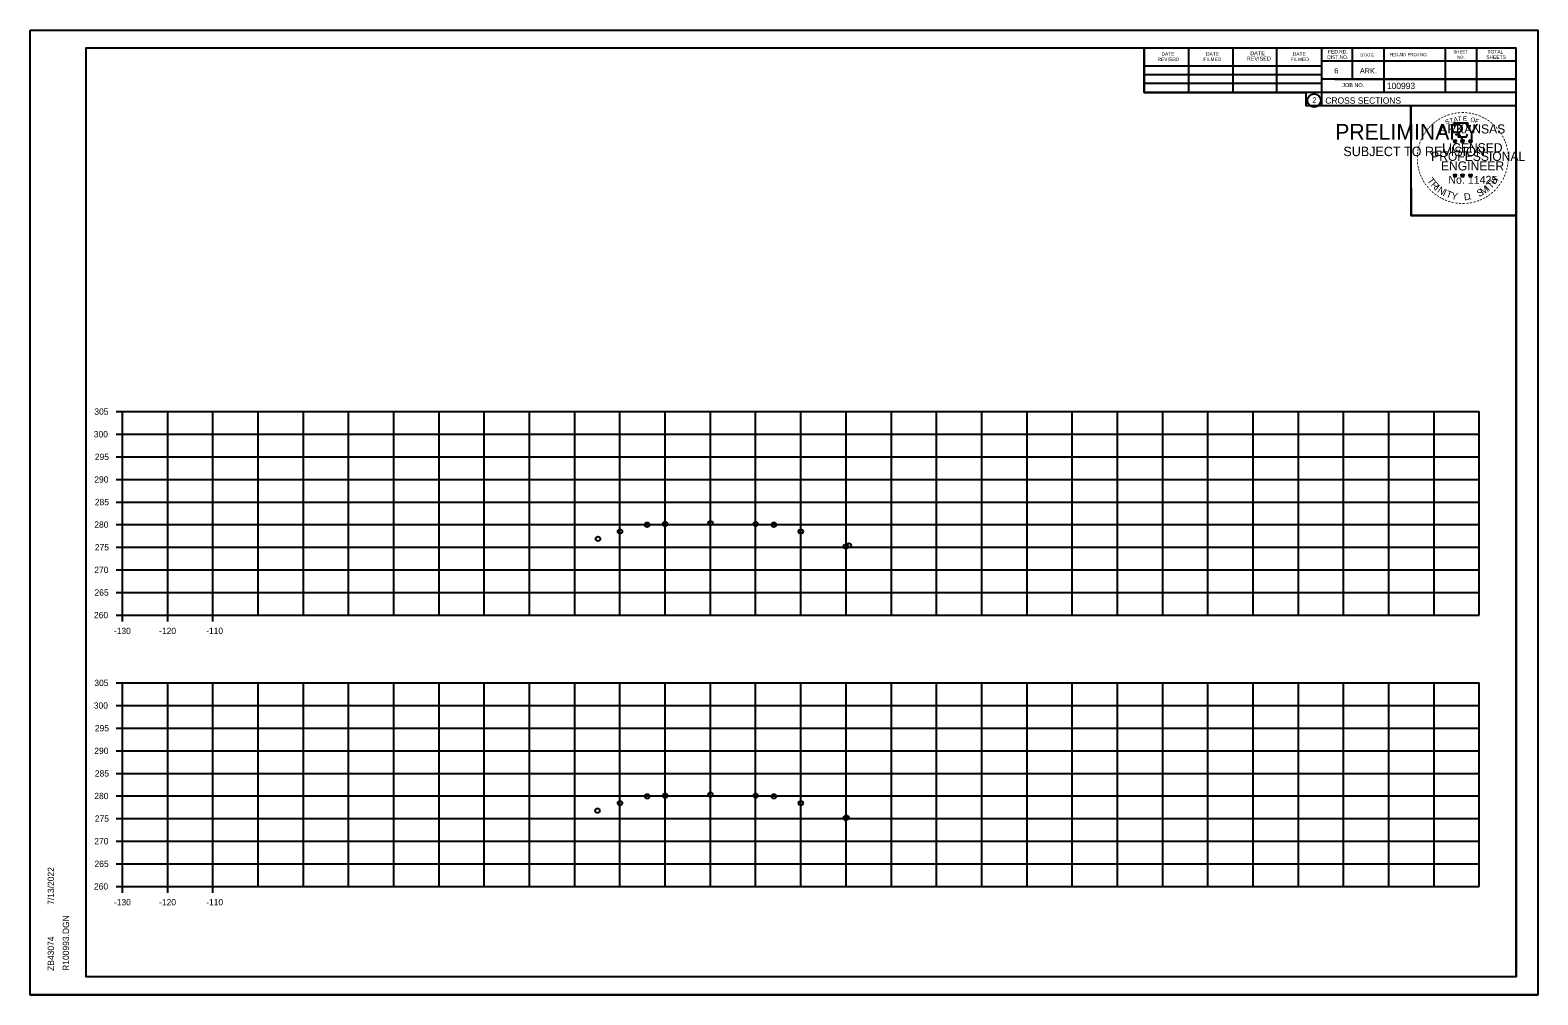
# Model space of a CAD drawing. Extents: x 4667 to 1632277, y -2100 to 724501.
# Drawn here: x 5969.1 to 6302.5, y -257.1 to -43.7 of the extents above; entities that cross this region are included whole.
import ezdxf

# ---------------------------------------------------------------- set-up
doc = ezdxf.new("R2010")
doc.units = 0
for name, color, linetype in [('R_Axis', 7, 'Continuous'), ('R_Axis Annot', 7, 'Continuous'), ('R_Grid', 7, 'Continuous'), ('R_No Plot', 7, 'Continuous')]:
    doc.layers.add(name, color=color, linetype=linetype)

msp = doc.modelspace()

# ---------------------------------------------------------------- linework, layer by layer
at = {"layer": 'R_Axis'}
for p, q in [((5988.12, -128.08), (5989.52, -128.08)), ((5989.52, -173.08), (5989.52, -128.08)), ((5988.12, -133.08), (5989.52, -133.08)), ((5988.12, -138.08), (5989.52, -138.08)), ((5988.12, -143.08), (5989.52, -143.08)), ((5988.12, -148.08), (5989.52, -148.08)), ((5988.12, -153.08), (5989.52, -153.08)), ((5988.12, -158.08), (5989.52, -158.08)), ((5988.12, -163.08), (5989.52, -163.08)), ((5988.12, -168.08), (5989.52, -168.08)), ((5988.12, -173.08), (5989.52, -173.08)), ((5989.52, -174.48), (5989.52, -173.08)), ((5999.52, -174.48), (5999.52, -173.08)), ((6009.52, -174.48), (6009.52, -173.08)), ((5988.12, -188.08), (5989.52, -188.08)), ((5989.52, -233.08), (5989.52, -188.08)), ((5988.12, -193.08), (5989.52, -193.08)), ((5988.12, -198.08), (5989.52, -198.08)), ((5988.12, -203.08), (5989.52, -203.08)), ((5988.12, -208.08), (5989.52, -208.08)), ((5988.12, -213.08), (5989.52, -213.08)), ((5988.12, -218.08), (5989.52, -218.08)), ((5988.12, -223.08), (5989.52, -223.08)), ((5988.12, -228.08), (5989.52, -228.08)), ((5988.12, -233.08), (5989.52, -233.08)), ((5989.52, -234.48), (5989.52, -233.08)), ((5999.52, -234.48), (5999.52, -233.08)), ((6009.52, -234.48), (6009.52, -233.08))]:
    msp.add_line(p, q, dxfattribs=at)
at = {"layer": 'R_Grid'}
for p, q in [((5989.52, -128.08), (6289.52, -128.08)), ((5989.52, -173.08), (5989.52, -128.08)), ((5999.52, -173.08), (5999.52, -128.08)), ((6009.52, -173.08), (6009.52, -128.08)), ((6019.52, -173.08), (6019.52, -128.08)), ((6029.52, -173.08), (6029.52, -128.08)), ((6039.52, -173.08), (6039.52, -128.08)), ((6049.52, -173.08), (6049.52, -128.08)), ((6059.52, -173.08), (6059.52, -128.08)), ((6069.52, -173.08), (6069.52, -128.08)), ((6079.52, -173.08), (6079.52, -128.08)), ((6089.52, -173.08), (6089.52, -128.08)), ((6099.52, -173.08), (6099.52, -128.08)), ((6109.52, -173.08), (6109.52, -128.08)), ((6119.52, -173.08), (6119.52, -128.08)), ((6129.52, -173.08), (6129.52, -128.08)), ((6139.52, -173.08), (6139.52, -128.08)), ((6149.52, -173.08), (6149.52, -128.08)), ((6159.52, -173.08), (6159.52, -128.08)), ((6169.52, -173.08), (6169.52, -128.08)), ((6179.52, -173.08), (6179.52, -128.08)), ((6189.52, -173.08), (6189.52, -128.08)), ((6199.52, -173.08), (6199.52, -128.08)), ((6209.52, -173.08), (6209.52, -128.08)), ((6219.52, -173.08), (6219.52, -128.08)), ((6229.52, -173.08), (6229.52, -128.08)), ((6239.52, -173.08), (6239.52, -128.08)), ((6249.52, -173.08), (6249.52, -128.08)), ((6259.52, -173.08), (6259.52, -128.08)), ((6269.52, -173.08), (6269.52, -128.08)), ((6279.52, -173.08), (6279.52, -128.08)), ((6289.52, -173.08), (6289.52, -128.08)), ((5989.52, -133.08), (6289.52, -133.08)), ((5989.52, -138.08), (6289.52, -138.08)), ((5989.52, -143.08), (6289.52, -143.08)), ((5989.52, -148.08), (6289.52, -148.08)), ((5989.52, -153.08), (6289.52, -153.08)), ((5989.52, -158.08), (6289.52, -158.08)), ((5989.52, -163.08), (6289.52, -163.08)), ((5989.52, -168.08), (6289.52, -168.08)), ((5989.52, -173.08), (6289.52, -173.08)), ((5989.52, -188.08), (6289.52, -188.08)), ((5989.52, -233.08), (5989.52, -188.08)), ((5999.52, -233.08), (5999.52, -188.08)), ((6009.52, -233.08), (6009.52, -188.08)), ((6019.52, -233.08), (6019.52, -188.08)), ((6029.52, -233.08), (6029.52, -188.08)), ((6039.52, -233.08), (6039.52, -188.08)), ((6049.52, -233.08), (6049.52, -188.08)), ((6059.52, -233.08), (6059.52, -188.08)), ((6069.52, -233.08), (6069.52, -188.08)), ((6079.52, -233.08), (6079.52, -188.08)), ((6089.52, -233.08), (6089.52, -188.08)), ((6099.52, -233.08), (6099.52, -188.08)), ((6109.52, -233.08), (6109.52, -188.08)), ((6119.52, -233.08), (6119.52, -188.08)), ((6129.52, -233.08), (6129.52, -188.08)), ((6139.52, -233.08), (6139.52, -188.08)), ((6149.52, -233.08), (6149.52, -188.08)), ((6159.52, -233.08), (6159.52, -188.08)), ((6169.52, -233.08), (6169.52, -188.08)), ((6179.52, -233.08), (6179.52, -188.08)), ((6189.52, -233.08), (6189.52, -188.08)), ((6199.52, -233.08), (6199.52, -188.08)), ((6209.52, -233.08), (6209.52, -188.08)), ((6219.52, -233.08), (6219.52, -188.08)), ((6229.52, -233.08), (6229.52, -188.08)), ((6239.52, -233.08), (6239.52, -188.08)), ((6249.52, -233.08), (6249.52, -188.08)), ((6259.52, -233.08), (6259.52, -188.08)), ((6269.52, -233.08), (6269.52, -188.08)), ((6279.52, -233.08), (6279.52, -188.08)), ((6289.52, -233.08), (6289.52, -188.08)), ((5989.52, -193.08), (6289.52, -193.08)), ((5989.52, -198.08), (6289.52, -198.08)), ((5989.52, -203.08), (6289.52, -203.08)), ((5989.52, -208.08), (6289.52, -208.08)), ((5989.52, -213.08), (6289.52, -213.08)), ((5989.52, -218.08), (6289.52, -218.08)), ((5989.52, -223.08), (6289.52, -223.08)), ((5989.52, -228.08), (6289.52, -228.08)), ((5989.52, -233.08), (6289.52, -233.08))]:
    msp.add_line(p, q, dxfattribs=at)
at = {"layer": 'R_No Plot'}
for p, q in [((5969.12, -43.72), (6302.46, -43.72)), ((5981.52, -47.62), (6297.7, -47.62)), ((5981.52, -253.08), (5981.52, -47.62)), ((6134.04, -47.88), (6134.04, -47.88)), ((6134.04, -47.88), (6134.04, -47.88)), ((6215.44, -57.5), (6215.44, -47.62)), ((6225.3, -57.5), (6225.3, -47.82)), ((6235.06, -57.5), (6235.06, -47.82)), ((6244.74, -57.5), (6244.74, -47.82)), ((6254.6, -47.62), (6254.6, -60.42)), ((6261.44, -47.62), (6261.44, -54.56)), ((6268.38, -47.62), (6268.38, -57.5)), ((6281.96, -47.62), (6281.96, -57.5)), ((6288.9, -47.62), (6288.9, -57.5)), ((6297.7, -253.08), (6297.7, -47.62)), ((6215.44, -51.64), (6254.6, -51.64)), ((6297.7, -50.56), (6254.6, -50.56)), ((6297.7, -50.54), (6297.7, -50.54)), ((6215.44, -53.5), (6254.6, -53.5)), ((6215.44, -57.5), (6215.44, -55.44)), ((6215.44, -55.44), (6254.6, -55.44)), ((6297.7, -54.56), (6254.6, -54.56)), ((6257.56, -54.56), (6297.7, -54.56)), ((6297.7, -57.5), (6215.44, -57.5)), ((6254.6, -60.42), (6297.7, -60.42)), ((6283.79, -68.16), (6284.14, -68.27)), ((6283.79, -68.16), (6284.04, -68.21)), ((6283.79, -68.16), (6284.03, -68.29)), ((6283.92, -68.57), (6284.14, -68.27)), ((6283.92, -68.57), (6284.05, -68.33)), ((6283.92, -68.57), (6284.14, -68.35)), ((6284.14, -67.91), (6284.1, -68.16)), ((6284.14, -68.27), (6284.14, -67.91)), ((6284.14, -67.91), (6284.19, -68.16)), ((6284.49, -68.16), (6284.14, -68.27)), ((6284.35, -68.57), (6284.14, -68.27)), ((6284.35, -68.57), (6284.14, -68.36)), ((6284.49, -68.16), (6284.2, -68.21)), ((6284.35, -68.57), (6284.21, -68.28)), ((6284.49, -68.16), (6284.28, -68.27)), ((6285.46, -68.16), (6285.81, -68.27)), ((6285.46, -68.16), (6285.71, -68.21)), ((6285.46, -68.16), (6285.7, -68.29)), ((6285.59, -68.57), (6285.81, -68.27)), ((6285.59, -68.57), (6285.72, -68.33)), ((6285.59, -68.57), (6285.81, -68.35)), ((6285.81, -67.91), (6285.77, -68.16)), ((6285.81, -68.27), (6285.81, -67.91)), ((6285.81, -67.91), (6285.86, -68.16)), ((6286.16, -68.16), (6285.81, -68.27)), ((6286.02, -68.57), (6285.81, -68.27)), ((6286.02, -68.57), (6285.81, -68.36)), ((6286.16, -68.16), (6285.87, -68.21)), ((6286.02, -68.57), (6285.88, -68.28)), ((6286.16, -68.16), (6285.95, -68.27)), ((6287.22, -68.18), (6287.57, -68.29)), ((6287.22, -68.18), (6287.48, -68.22)), ((6287.22, -68.18), (6287.46, -68.3)), ((6287.36, -68.58), (6287.57, -68.29)), ((6287.36, -68.58), (6287.48, -68.34)), ((6287.36, -68.58), (6287.57, -68.37)), ((6287.57, -67.92), (6287.53, -68.17)), ((6287.57, -68.29), (6287.57, -67.92)), ((6287.57, -67.92), (6287.62, -68.17)), ((6287.92, -68.18), (6287.57, -68.29)), ((6287.79, -68.58), (6287.57, -68.29)), ((6287.79, -68.58), (6287.57, -68.37)), ((6287.92, -68.18), (6287.63, -68.22)), ((6287.79, -68.58), (6287.65, -68.29)), ((6287.92, -68.18), (6287.72, -68.28)), ((6283.79, -75.74), (6284.13, -75.85)), ((6283.79, -75.74), (6284.04, -75.78)), ((6283.79, -75.74), (6284.02, -75.86)), ((6283.92, -76.14), (6284.13, -75.85)), ((6283.92, -76.14), (6284.04, -75.9)), ((6283.92, -76.14), (6284.13, -75.93)), ((6284.13, -75.48), (6284.09, -75.73)), ((6284.13, -75.85), (6284.13, -75.48)), ((6284.13, -75.48), (6284.18, -75.73)), ((6284.48, -75.74), (6284.13, -75.85)), ((6284.35, -76.14), (6284.13, -75.85)), ((6284.35, -76.14), (6284.13, -75.93)), ((6284.48, -75.74), (6284.2, -75.79)), ((6284.35, -76.14), (6284.21, -75.85)), ((6284.48, -75.74), (6284.28, -75.84)), ((6285.45, -75.74), (6285.8, -75.85)), ((6285.45, -75.74), (6285.71, -75.78)), ((6285.45, -75.74), (6285.69, -75.86)), ((6285.59, -76.14), (6285.8, -75.85)), ((6285.59, -76.14), (6285.71, -75.9)), ((6285.59, -76.14), (6285.8, -75.93)), ((6285.8, -75.48), (6285.76, -75.73)), ((6285.8, -75.85), (6285.8, -75.48)), ((6285.8, -75.48), (6285.85, -75.73)), ((6286.15, -75.74), (6285.8, -75.85)), ((6286.02, -76.14), (6285.8, -75.85)), ((6286.02, -76.14), (6285.8, -75.93)), ((6286.15, -75.74), (6285.86, -75.79)), ((6286.02, -76.14), (6285.88, -75.85)), ((6286.15, -75.74), (6285.95, -75.84)), ((6287.22, -75.75), (6287.57, -75.86)), ((6287.22, -75.75), (6287.47, -75.79)), ((6287.22, -75.75), (6287.46, -75.87)), ((6287.35, -76.15), (6287.57, -75.86)), ((6287.35, -76.15), (6287.48, -75.91)), ((6287.35, -76.15), (6287.57, -75.94)), ((6287.57, -75.49), (6287.53, -75.74)), ((6287.57, -75.86), (6287.57, -75.49)), ((6287.57, -75.49), (6287.62, -75.74)), ((6287.92, -75.75), (6287.57, -75.86)), ((6287.78, -76.15), (6287.57, -75.86)), ((6287.78, -76.15), (6287.57, -75.94)), ((6287.92, -75.75), (6287.63, -75.8)), ((6287.78, -76.15), (6287.65, -75.86)), ((6287.92, -75.75), (6287.71, -75.85)), ((6273.74, -82.87), (6273.74, -82.87)), ((5981.52, -253.08), (5981.52, -253.08)), ((6297.7, -253.08), (5981.52, -253.08)), ((5969.12, -257.06), (6302.46, -257.06))]:
    msp.add_line(p, q, dxfattribs=at)
for points in [[(5969.12, -43.72), (6302.46, -43.72), (6302.46, -257.06), (5969.12, -257.06)], [(6215.44, -47.62), (6215.44, -57.5), (6251.18, -57.5), (6251.18, -60.42), (6274.38, -60.42), (6274.38, -84.75), (6297.7, -84.75), (6297.7, -253.08), (5981.52, -253.08), (5981.52, -47.62)], [(6274.38, -60.42), (6297.58, -60.42), (6297.7, -84.75), (6274.5, -84.75)]]:
    msp.add_lwpolyline(points, close=True, dxfattribs=at)
for points in [[(6283.83, -64.29), (6284.1, -65.11)], [(6287.34, -65.21), (6287.48, -64.92), (6286.8, -64.95), (6286.95, -64.29), (6283.83, -64.29)], [(6284.14, -67.91), (6284.35, -68.57), (6283.79, -68.16), (6284.49, -68.16), (6283.92, -68.57), (6284.14, -67.91)], [(6284.32, -66.71), (6284.32, -66.8), (6284.89, -66.81), (6284.83, -67.29), (6286.7, -67.29), (6286.9, -66.75)], [(6285.81, -67.91), (6286.02, -68.57), (6285.46, -68.16), (6286.16, -68.16), (6285.59, -68.57), (6285.81, -67.91)], [(6287.57, -67.92), (6287.79, -68.58), (6287.22, -68.18), (6287.92, -68.18), (6287.36, -68.58), (6287.57, -67.92)], [(6284.13, -75.48), (6284.35, -76.14), (6283.79, -75.74), (6284.48, -75.74), (6283.92, -76.14), (6284.13, -75.48)], [(6285.8, -75.48), (6286.02, -76.14), (6285.45, -75.74), (6286.15, -75.74), (6285.59, -76.14), (6285.8, -75.48)], [(6287.57, -75.49), (6287.78, -76.15), (6287.22, -75.75), (6287.92, -75.75), (6287.35, -76.15), (6287.57, -75.49)]]:
    msp.add_lwpolyline(points, dxfattribs=at)
for centre, radius in [((6252.99, -59.28), 1.47), ((6284.14, -68.28), 0.172), ((6284.14, -68.28), 0.145), ((6284.14, -68.28), 0.116), ((6284.14, -68.28), 0.0991), ((6284.14, -68.28), 0.0747), ((6284.14, -68.28), 0.0495), ((6284.14, -68.28), 0.0296), ((6285.81, -68.28), 0.172), ((6285.81, -68.28), 0.145), ((6285.81, -68.28), 0.116), ((6285.81, -68.28), 0.0991), ((6285.81, -68.28), 0.0747), ((6285.81, -68.28), 0.0495), ((6285.81, -68.28), 0.0296), ((6287.57, -68.29), 0.172), ((6287.57, -68.29), 0.145), ((6287.57, -68.29), 0.116), ((6287.57, -68.29), 0.0991), ((6287.57, -68.29), 0.0747), ((6287.57, -68.29), 0.0495), ((6287.57, -68.29), 0.0296), ((6284.13, -75.85), 0.172), ((6284.13, -75.85), 0.145), ((6284.13, -75.85), 0.116), ((6284.13, -75.85), 0.0991), ((6284.13, -75.85), 0.0747), ((6284.13, -75.85), 0.0495), ((6284.13, -75.85), 0.0296), ((6285.8, -75.85), 0.172), ((6285.8, -75.85), 0.145), ((6285.8, -75.85), 0.116), ((6285.8, -75.85), 0.0991), ((6285.8, -75.85), 0.0747), ((6285.8, -75.85), 0.0495), ((6285.8, -75.85), 0.0296), ((6287.57, -75.86), 0.172), ((6287.57, -75.86), 0.145), ((6287.57, -75.86), 0.116), ((6287.57, -75.86), 0.0991), ((6287.57, -75.86), 0.0747), ((6287.57, -75.86), 0.0495), ((6287.57, -75.86), 0.0296), ((6105.52, -153.1), 0.5), ((6109.52, -152.94), 0.5), ((6119.52, -152.74), 0.5), ((6129.52, -152.94), 0.5), ((6133.52, -153.1), 0.5), ((6094.66, -156.22), 0.5), ((6099.52, -154.6), 0.5), ((6139.52, -154.6), 0.5), ((6149.47, -157.91), 0.5), ((6150.12, -157.7), 0.5), ((6105.52, -213.16), 0.5), ((6109.52, -213), 0.5), ((6119.52, -212.8), 0.5), ((6129.52, -213), 0.5), ((6133.52, -213.16), 0.5), ((6094.54, -216.32), 0.5), ((6099.52, -214.66), 0.5), ((6139.52, -214.66), 0.5), ((6149.43, -217.96), 0.5), ((6149.64, -217.89), 0.5)]:
    msp.add_circle(centre, radius, dxfattribs=at)

# ---------------------------------------------------------------- texts
at = {"layer": 'R_Axis Annot'}
for s, p in [('305', (5983.31, -128.78)), ('300', (5983.19, -133.78)), ('295', (5983.42, -138.78)), ('290', (5983.3, -143.78)), ('285', (5983.42, -148.78)), ('280', (5983.3, -153.78)), ('275', (5983.42, -158.78)), ('270', (5983.3, -163.78)), ('265', (5983.35, -168.78)), ('260', (5983.23, -173.78)), ('-130', (5987.63, -177.28)), ('-120', (5997.63, -177.28)), ('-110', (6008.03, -177.28)), ('305', (5983.31, -188.78)), ('300', (5983.19, -193.78)), ('295', (5983.42, -198.78)), ('290', (5983.3, -203.78)), ('285', (5983.42, -208.78)), ('280', (5983.3, -213.78)), ('275', (5983.42, -218.78)), ('270', (5983.3, -223.78)), ('265', (5983.35, -228.78)), ('260', (5983.23, -233.78)), ('-130', (5987.63, -237.28)), ('-120', (5997.63, -237.28)), ('-110', (6008.03, -237.28))]:
    msp.add_text(s, height=1.4, dxfattribs=at).set_placement(p)
at = {"layer": 'R_No Plot'}
for s, height, rotation, p in [('REVISED', 0.782, 360, (6218.36, -50.56)), ('DATE', 0.782, 360, (6219.24, -49.38)), ('FILMED', 0.782, 360, (6228.52, -50.56)), ('DATE', 0.782, 360, (6229.1, -49.38)), ('REVISED', 0.879, 360, (6238.1, -50.46)), ('DATE', 0.879, 360, (6238.88, -49.28)), ('FILMED', 0.782, 360, (6247.86, -50.56)), ('DATE', 0.782, 360, (6248.26, -49.38)), ('DIST.NO.', 0.782, 360, (6255.88, -50.08)), ('FED.RD.', 0.782, 360, (6256.08, -48.9)), ('STATE', 0.684, 360, (6263.2, -49.58)), ('FED.AID PROJ.NO.', 0.684, 360, (6269.66, -49.48)), ('SHEET', 0.684, 360, (6283.82, -48.9)), ('NO.', 0.684, 360, (6284.6, -50.08)), ('SHEETS', 0.782, 360, (6291.06, -50.08)), ('TOTAL', 0.782, 360, (6291.34, -48.9)), ('6', 1.17, 360, (6257.44, -53.3)), ('ARK.', 1.172, 360, (6263.1, -53.3)), ('JOB NO.', 0.879, 360, (6259.2, -56.32)), ('100993', 1.4, 360, (6269.08, -56.76)), ('2', 1.17, 360, (6252.61, -59.77)), ('CROSS SECTIONS', 1.4, 360, (6255.47, -59.99)), ('-', 1.6, 34.0636, (6280.71, -64.11)), ('-', 1.6, 28.7918, (6281.31, -63.74)), ('-', 1.6, 24.3072, (6281.94, -63.43)), ('-', 1.6, 19.1761, (6282.58, -63.16)), ('T', 1, 16.4036, (6283.1, -64.28)), ('-', 1.6, 13.6301, (6283.33, -62.92)), ('A', 1, 11.2132, (6283.92, -64.03)), ('-', 1.6, 10.2193, (6284.01, -62.76)), ('T', 1, 6.0228, (6284.77, -63.86)), ('-', 1.6, 5.8968, (6284.73, -62.65)), ('-', 1.6, 0.1862, (6285.51, -62.57)), ('E', 1, 0.8323, (6285.88, -63.75)), ('-', 1.6, 357.743, (6286.23, -62.59)), ('-', 1.6, 352.1617, (6286.97, -62.64)), ('O', 1, 350.4515, (6287.48, -63.96)), ('-', 1.6, 347.2049, (6287.69, -62.76)), ('F', 1, 340.0707, (6288.44, -64.19)), ('-', 1.6, 342.3362, (6288.33, -62.91)), ('-', 1.6, 337.8551, (6289.06, -63.13)), ('-', 1.6, 334.1211, (6289.69, -63.41)), ('-', 1.6, 329.6409, (6290.27, -63.69)), ('PRELIMINARY', 3.5, 360, (6257.66, -67.96)), ('DWB', 0.01, 360, (6258.4, -66.11)), ('-', 1.6, 58.0706, (6277.64, -67.36)), ('-', 1.6, 54.2325, (6277.96, -66.84)), ('-', 1.6, 50.6142, (6278.38, -66.27)), ('-', 1.6, 48.423, (6278.78, -65.78)), ('-', 1.6, 42.9622, (6279.23, -65.3)), ('-', 1.6, 38.9507, (6279.66, -64.89)), ('-', 1.6, 36.2317, (6280.14, -64.51)), ('ARKANSAS', 2, 360, (6280.68, -66.57)), ('S', 1, 21.594, (6282.18, -64.61)), ('-', 1.6, 325.8627, (6290.92, -64.05)), ('-', 1.6, 320.5297, (6291.53, -64.48)), ('-', 1.6, 315.5786, (6292.12, -64.96)), ('-', 1.6, 309.8797, (6292.69, -65.51)), ('-', 1.6, 306.6522, (6293.22, -66.12)), ('-', 1.4, 303.6753, (6293.7, -66.68)), ('SUBJECT TO REVISION', 2.0751, 360, (6259.46, -71.58)), ('-', 1.6, 81.2013, (6276.52, -70.64)), ('-', 1.6, 75.461, (6276.65, -69.93)), ('-', 1.6, 72.3945, (6276.85, -69.22)), ('-', 1.6, 67.7743, (6277.07, -68.59)), ('-', 1.6, 62.8713, (6277.32, -67.98)), ('LICENSED', 2, 360, (6281.28, -70.72)), ('DWB', 0.01, 360, (6284.13, -68.28)), ('DWB', 0.01, 360, (6285.8, -68.28)), ('DWB', 0.01, 360, (6287.56, -68.29)), ('-', 1.6, 299.6684, (6294.02, -67.29)), ('-', 1.6, 294.6628, (6294.35, -67.9)), ('-', 1.6, 290.5728, (6294.6, -68.48)), ('-', 1.6, 285.1233, (6294.84, -69.06)), ('-', 1.6, 280.5493, (6295.04, -69.8)), ('-', 1.6, 94.1959, (6276.45, -72.76)), ('-', 1.6, 89.0622, (6276.42, -72.04)), ('-', 1.6, 98.9479, (6276.52, -73.43)), ('-', 1.6, 85.1863, (6276.44, -71.34)), ('PROFESSIONAL', 2, 360, (6278.86, -72.63)), ('ENGINEER', 2, 360, (6281.04, -74.75)), ('-', 1.6, 263.5172, (6295.28, -72.59)), ('-', 1.6, 276.5962, (6295.2, -70.57)), ('-', 1.6, 274.3301, (6295.26, -71.29)), ('-', 1.6, 269.9407, (6295.29, -71.92)), ('-', 1.6, 101.7149, (6276.66, -74.16)), ('-', 1.6, 105.4578, (6276.82, -74.76)), ('-', 1.6, 109.0874, (6277.04, -75.39)), ('-', 1.6, 114.0643, (6277.29, -75.98)), ('-', 1.6, 115.7289, (6277.59, -76.6)), ('T', 1.54, 306.0406, (6277.89, -77.01)), ('No. 11425', 1.757, 360, (6282.67, -77.7)), ('DWB', 0.01, 360, (6284.12, -75.85)), ('DWB', 0.01, 360, (6285.79, -75.85)), ('DWB', 0.01, 360, (6287.56, -75.86)), ('H', 1.54, 54.6088, (6293.01, -77.97)), ('-', 1.6, 244.6197, (6294.43, -75.94)), ('-', 1.6, 247.8887, (6294.69, -75.31)), ('-', 1.6, 252.8681, (6294.91, -74.64)), ('-', 1.6, 255.7626, (6295.09, -73.92)), ('-', 1.6, 260.9953, (6295.2, -73.24)), ('-', 1.6, 120.4471, (6277.95, -77.19)), ('-', 1.6, 125.8934, (6278.35, -77.75)), ('-', 1.6, 130.7181, (6278.82, -78.3)), ('-', 1.6, 134.2238, (6279.33, -78.85)), ('R', 1.54, 314.005, (6278.66, -78.06)), ('-', 1.6, 138.9338, (6279.86, -79.31)), ('-', 1.6, 144.6463, (6280.41, -79.72)), ('I', 1.54, 321.9694, (6279.56, -78.99)), ('N', 1.54, 326.5002, (6280.12, -79.46)), ('I', 1.54, 335.3603, (6281.33, -80.25)), ('T', 1.54, 339.8912, (6281.99, -80.57)), ('Y', 1.54, 347.8556, (6283.21, -81.02)), ('D', 1.54, 6.3969, (6286.19, -81.38)), ('S', 1.54, 26.9312, (6289.44, -80.65)), ('M', 1.54, 32.6563, (6290.28, -80.24)), ('I', 1.54, 42.1136, (6291.56, -79.39)), ('T', 1.54, 46.6444, (6292.12, -78.92)), ('-', 1.6, 215.7363, (6291.65, -79.46)), ('-', 1.6, 221.0851, (6292.2, -78.99)), ('-', 1.6, 225.7653, (6292.72, -78.48)), ('-', 1.6, 231.2538, (6293.2, -77.91)), ('-', 1.6, 233.8452, (6293.63, -77.35)), ('-', 1.6, 239.0712, (6294.03, -76.7)), ('-', 1.6, 148.0898, (6280.98, -80.09)), ('-', 1.6, 151.5704, (6281.55, -80.41)), ('-', 1.6, 154.6002, (6282.08, -80.66)), ('-', 1.6, 158.5612, (6282.7, -80.91)), ('-', 1.6, 162.7983, (6283.39, -81.13)), ('-', 1.6, 167.5555, (6284.1, -81.29)), ('-', 1.6, 173.1155, (6284.87, -81.4)), ('-', 1.6, 176.5183, (6285.62, -81.45)), ('-', 1.6, 181.5918, (6286.37, -81.43)), ('-', 1.6, 185.8167, (6287.18, -81.36)), ('-', 1.6, 191.2858, (6287.91, -81.23)), ('.', 1.54, 13.7642, (6287.39, -81.25)), ('-', 1.6, 195.4743, (6288.64, -81.03)), ('-', 1.6, 200.7184, (6289.32, -80.78)), ('-', 1.6, 204.2516, (6289.94, -80.51)), ('-', 1.6, 207.3568, (6290.56, -80.19)), ('-', 1.6, 212.2491, (6291.12, -79.85)), ('7/13/2022', 1.4, 90, (5974.39, -237.15)), ('R100993.DGN', 1.4, 90, (5977.72, -251.75)), ('ZB43074', 1.4, 90, (5974.39, -251.75))]:
    msp.add_text(s, height=height, rotation=rotation, dxfattribs=at).set_placement(p)

doc.saveas('drawing.dxf')
